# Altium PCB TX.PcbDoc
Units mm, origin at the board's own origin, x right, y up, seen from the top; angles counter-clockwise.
Board outline 26 x 26 mm, 2 copper layers (Top, Bottom), stack 0.323 mm thick; 37 components, 25 nets, 114 pads, 97 vias.
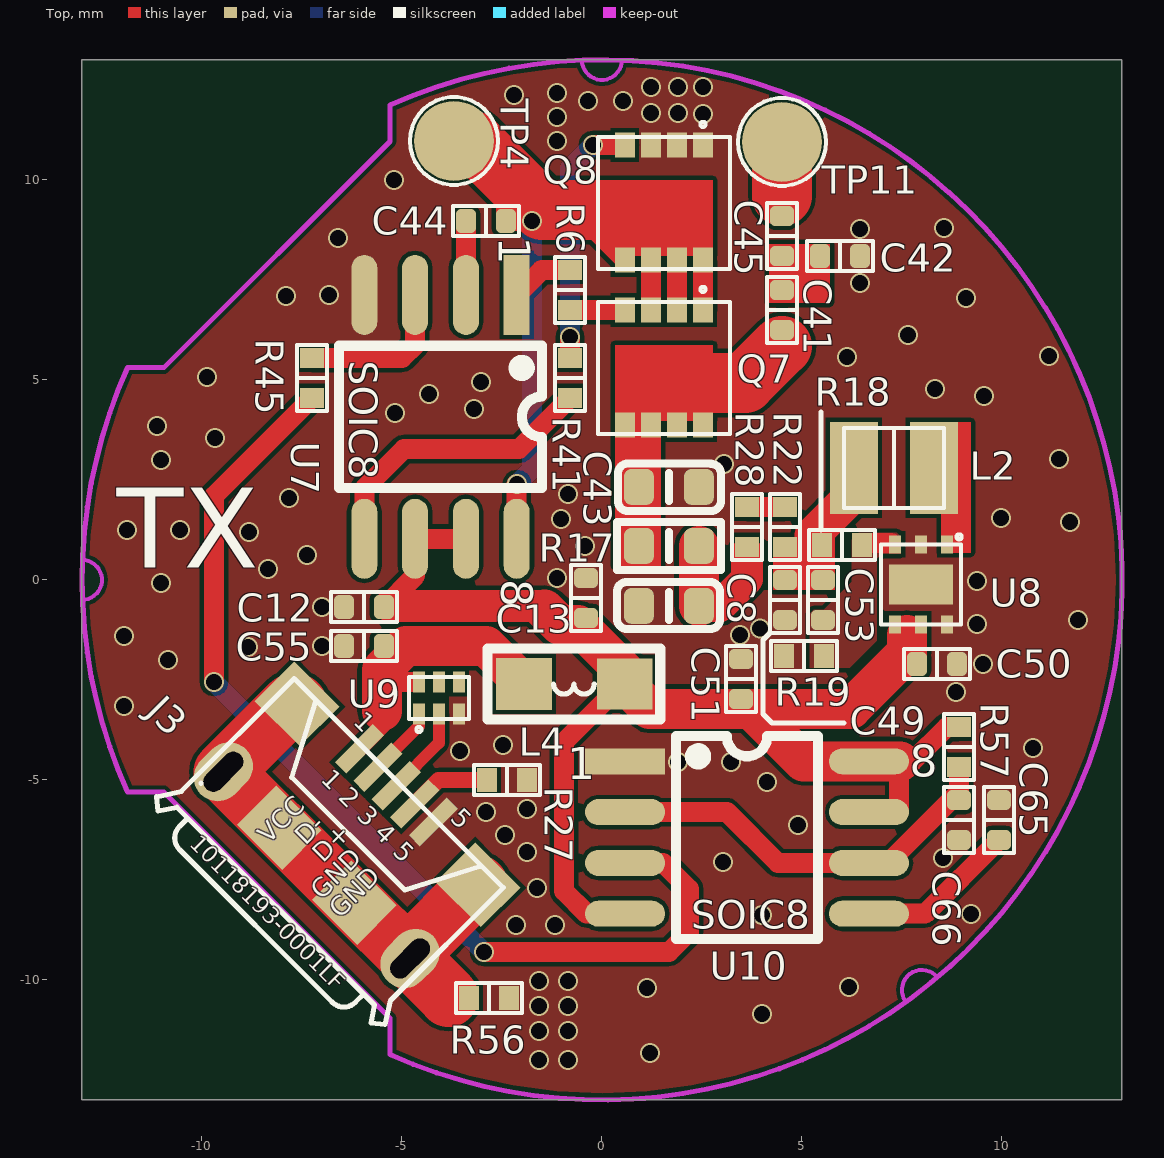
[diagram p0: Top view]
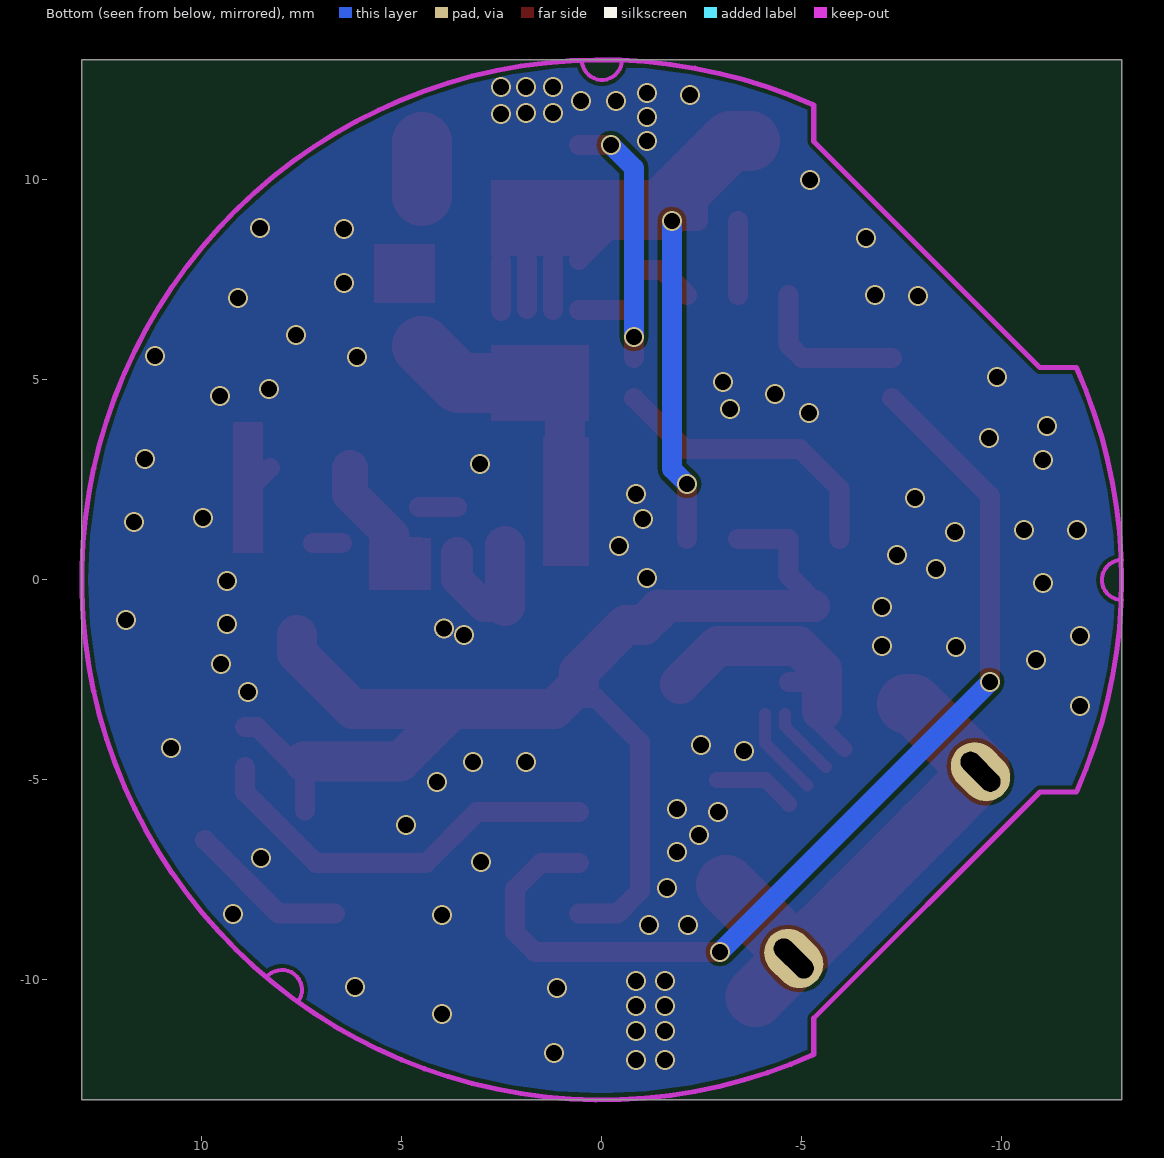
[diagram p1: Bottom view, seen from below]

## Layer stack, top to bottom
Top: signal copper 0.0343
Dielectric: core 0.254, FR-4, Dk 4.3
Bottom: signal copper 0.0343

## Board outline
-13,-13 13,-13 13,-5.875 13,13 -13,13 -13,-13

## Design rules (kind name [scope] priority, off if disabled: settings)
Clearance [All] p1: gap=0.1
Clearance "'Default' PADS rule_18" [All] p2: gap=0.152
Clearance "'Default' PADS rule_15" [IsVia vs IsVia] p3: gap=0.152
ComponentClearance "'Default' PADS rule_12" [All] p1 off: gap=0 collisioncheckmode=3 verticalgap=0 showdistances=FALSE
DiffPairsRouting [All] p1 off: maxlimit=0.254 minlimit=0.254 mostfreqgap=0.254 maxuncoupledlength=12.7
FabricationTestPointUsage TestPointUsage [All] p1 off: valid=0 allowmultiple=FALSE
FabricationTestpoint Testpoint [(IsPad And (OnTopLayer Or OnBottomLayer))] p1 off: side=3 testpointundercomponent=TRUE minsize=1.016 maxsize=2.54 preferedsize=1.524 minholesize=0 maxholesize=1.016 preferedholesize=0.813 testpointgrid=0.025 allowsidetop=TRUE allowsidebottom=TRUE usegrid=TRUE gridtolerance=0
FanoutControl Fanout_BGA [IsBGA] p1 off: bgadir=Out bgaviamode=Centered fanoutstyle=Auto fanoutdirection=Alternating viagrid=0.025 // Fanout_BGA (Default Rule)
FanoutControl Fanout_LCC [IsLCC] p2 off: bgadir=Out bgaviamode=Centered fanoutstyle=Auto fanoutdirection=Alternating viagrid=0.025 // Fanout_LCC (Default Rule)
FanoutControl Fanout_SOIC [IsSOIC] p3 off: bgadir=Out bgaviamode=Centered fanoutstyle=Auto fanoutdirection=Alternating viagrid=0.025 // Fanout_SOIC (Default Rule)
FanoutControl Fanout_Small [(CompPinCount < 5)] p4 off: bgadir=Out bgaviamode=Centered fanoutstyle=Auto fanoutdirection=OutThenIn viagrid=0.025 // Fanout_Small (Default Rule)
FanoutControl Fanout_Default [All] p5 off: bgadir=Out bgaviamode=Centered fanoutstyle=Auto fanoutdirection=Alternating viagrid=0.025 // Fanout_Default (Default Rule)
FlightTimeFalling "'Default' PADS rule_10" [All] p1 off: maximum=10.00
FlightTimeRising "'Default' PADS rule_9" [All] p1 off: maximum=10.00
Height [All] p1 off: minheight=0 maxheight=25.4 prefheight=12.7
HoleSize [All] p1 off: absolutevalues=TRUE maxlimit=2.54 minlimit=0.025 maxpercent=80.000 minpercent=20.000
LayerPairs [All] p1 off: enforce=TRUE
Length "'Default' PADS rule_5" [All] p1 off: maxlimit=1270 minlimit=0
MatchedLengths "'Default' PADS rule_11" [InNetClass('All Nets')] p1 off: tolerance=5.08 checknetsindiffpair=TRUE checkdiffpairvsdiffpair=TRUE checkothers=TRUE
MaxMinImpedance "'Default' PADS rule_8" [All] p1 off: minimum=50.00 maximum=150.0
ParallelSegment "'Default' PADS rule_7" [All] p1 off: limit=25.4 gap=5.08
ParallelSegment "'Default' PADS rule_6" [All] p2 off: limit=25.4 gap=5.08
PasteMaskExpansion [All] p1 off: expansion=0
PlaneClearance "'Default' PADS rule_14" [All] p1 off: clearance=0.152
PlaneConnect "Power Plane Connect Style - from global settings" [All] p1: planeconnectstyle=Direct reliefexpansion=0.508 reliefentries=2 reliefconductorwidth=0.381 reliefairgap=0.254
PolygonConnect [All] p1: connectstyle=Direct reliefconductorwidth=0.254 reliefentries=4 polygonreliefangle="90 Angle" airgapwidth=0.254
RoutingCorners [All] p1 off: cornerstyle=45-Degree minsetback=2.54 maxsetback=2.54
RoutingLayers "'Default' PADS rule_3" [All] p1 off: top layer_v5=TRUE bottom layer_v5=TRUE
RoutingPriority "'Default' PADS rule_2" [All] p1 off: routingpriority=3
RoutingTopology "'Default' PADS rule" [All] p1 off: topology=Shortest
RoutingVias "'Default' PADS rule_4" [All] p1: holewidth=0.94 width=0.4 viastyle="Through Hole" minholewidth=0.2 minwidth=0.3 maxholewidth=2 maxwidth=1.397
SMDToCorner "'Default' PADS rule_16" [All] p1 off: distance=60000
SMDToPlane "'Default' PADS rule_17" [All] p1 off: distance=60000
SolderMaskExpansion [All] p1 off: expansion=0.102
Width "'Default' PADS rule_13" [All] p1: maxlimit=2 minlimit=0.1 preferedwidth=0.2
9 further rules are at their usual default settings.

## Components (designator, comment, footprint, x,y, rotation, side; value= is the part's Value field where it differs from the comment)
C8 "22uF" 0603CS 1.675,-0.65 r0 top
C12 "0.1uF" 0402C -5.95,-0.675 r180 top
C13 "10uF" 0402C -0.4,-0.45 r90 top
C41 "0.047uF" 0402C 4.5,6.75 r90 top
C42 "0.047uF" 0402C 5.95,8.1 r0 top
C43 "22uF" 0603CS 1.675,2.325 r180 top
C44 "0.22uF" 0402C -2.9,8.975 r0 top
C45 "0.01uF" 0402C 4.5,8.6 r90 top
C49 "10uF" 0402C 4.575,-0.5 r270 top
C50 "4.7uF" 0402C 8.375,-2.1 r0 top
C51 "10uF" 0402C 3.475,-2.475 r90 top
C53 "12pF" 0402C 5.525,-0.5 r270 top
C55 "10nF" 0402C -5.95,-1.65 r180 top
C65 "0.1uF" 0402C 9.925,-6 r90 top
C66 "0.1uF" 0402C 8.925,-6 r270 top
J3 "10118193-0001LF" 10118193-0001LF -8.65,-8.65 r315 top
L2 "2.2uH, LQH2HPN2R2MM0L" 2520-1 7.3,2.8 r180 top
L4 "BK2125HS101-T" 0805L -0.7,-2.6 r180 top
Q7 "CSD17308Q3" SSON_3.3*3.3 1.55,5.3 r270 top
Q8 "CSD17308Q3" SSON_3.3*3.3 1.55,9.425 r270 top
R6 "27" 0402R -0.8,7.25 r270 top
R17 "0.02" 0603RS 1.675,0.85 r0 top
R18 "600k" 0402R 6,0.875 r180 top
R19 "100k" 0402R 5.05,-1.9 r0 top
R22 "0" 0402R 4.575,1.325 r90 top
R27 "0" 0402R -2.375,-5 r0 top
R28 "0" 0402R 3.625,1.325 r90 top
R41 "27" 0402R -0.8,5.05 r90 top
R45 "10" 0402R -7.25,5.05 r90 top
R56 "0" 0402R -2.825,-10.45 r0 top
R57 "14.7" 0402R 8.925,-4.175 r90 top
TP4 "Probe_pad_1mm" PAD -3.7,10.975 r90 top
TP11 "Probe_pad_1mm" PAD 4.5,10.95 r0 top
U7 "TPS28225D" SOIC8 -2.13,7.125 r270 top
U8 "MM3472XRRE_SSON-6L" SSON-6L 7.981,-0.112 r270 top
U9 "TPD4E004" SON6 -4.075,-2.95 r90 top
U10 "LMC555" SOIC8 0.579,-4.535 r0 top

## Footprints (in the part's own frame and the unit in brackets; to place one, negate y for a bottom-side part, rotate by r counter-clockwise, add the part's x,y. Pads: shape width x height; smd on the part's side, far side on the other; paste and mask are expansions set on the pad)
0402C [mm]
  rrect50% 0.5x0.6 smd: 1(-0.5,0) 2(0.5,0)
  silkscreen extent -0.82,-0.38 0.82,0.38
0402R [mm]
  rect 0.5x0.6 smd: 1(-0.5,0) 2(0.5,0)
  silkscreen extent -0.82,-0.38 0.82,0.38
0603CS [mm]
  rrect50% 0.75x0.9 smd: 1(-0.75,0) 2(0.75,0)
  silkscreen extent -1.3,-0.58 1.28,0.6
0603RS [mm]
  rrect50% 0.75x0.9 smd: 1(-0.75,0) 2(0.75,0)
  silkscreen extent -1.3,-0.6 1.3,0.6
0805L [mm]
  rect 1.397x1.27 smd: 1(-1.27,0)
  rect 1.4x1.3 smd: 2(1.25,0)
  silkscreen extent -2.16,-0.89 2.16,0.89
2520-1 [mm]
  rect 1.2x2.3 smd: 1(-1,0) 2(1,0)
  silkscreen extent -1.25,-1 1.25,1
10118193-0001LF [mm]
  rect 0.4x1.35 smd: 1(-1.3,4.963) 2(-0.65,4.963) 3(0,4.961) 4(0.65,4.963) 5(1.3,4.975)
  rect 1.6x1.4 smd: 6(-3.2,4.65) 7(3.2,4.65) 8(1.325,2.15) 9(-1.325,2.15)
  oval 1.2x1.6 hole 0.5 slot 1.2 at 90 deg: 8(3.3,2.15) 9(-3.3,2.15)
  silkscreen extent -4.04,0 4.03,5.05
PAD [mm]
  round 2 smd: 1(0,0)
SOIC8 [mm]
  rect 2x0.65 smd: 1(0,0)
  oval 2x0.65 smd: 2(0,-1.27) 3(0,-2.54) 4(0,-3.81) 5(6.096,-3.81) 6(6.096,-2.54) 7(6.096,-1.27) 8(6.096,0)
  silkscreen extent 1.27,-4.44 4.83,0.64
SON6 [mm]
  rect 0.52x0.3 smd: 1(-0.4,0.5) 2(-0.4,0) 3(-0.4,-0.5) 4(0.4,-0.5) 5(0.4,0) 6(0.4,0.5)
  silkscreen extent -0.85,-0.75 0.53,0.75
SSON-6L [mm]
  rect 0.45x0.3 smd: 1(-1,0.65) 2(-1,0) 3(-1,-0.65) 4(1,-0.65) 5(1,0) 6(1,0.65)
  rect 1x1.6 smd: 7(0,0)
  silkscreen extent -1.25,-1 1,1.01
SSON_3.3*3.3 [mm]
  rect 0.63x0.5 smd: 1(-1.45,0.975) 2(-1.45,0.325) 3(-1.45,-0.325) 4(-1.45,-0.975) 5(1.425,-0.975) 6(1.425,-0.325) 7(1.425,0.325) 8(1.425,0.975)
  Top region: -0.575,-1.224 1.325,-1.224 1.325,1.226 -0.575,1.226
  silkscreen extent -2.03,-1.65 1.65,1.65

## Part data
C8 C12 C13 C41 C42 C43 C44 C45 C49 C50 C51 C53 C55 C65 C66: library part CAP_2.2nF_X7R_0603
J3: library part 10118193-0001LF_MUSB_1
L2: library part MLZ1005M2R2W_Ind402_0
L4: library part INDUCTOR/SM
R6 R17 R18 R19 R41 R57: library part RES_10K_0603_THK_1%
R22 R27 R28 R45 R56: library part RES_1oHM_0603
TP4 TP11: library part "TEST POINT"
U7: library part sn74lvc1g74dqer_0
U8: library part MM3472XRRE-6P_4

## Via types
v1: diameter 0.5, hole 0.4, Top to Bottom, tented both sides, 97 vias

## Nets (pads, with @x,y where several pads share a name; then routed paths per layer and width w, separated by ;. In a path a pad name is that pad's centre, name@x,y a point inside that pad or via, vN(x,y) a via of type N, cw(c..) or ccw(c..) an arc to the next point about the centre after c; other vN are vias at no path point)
GND: C8.1 C12.2 C13.2 C42.2 C43.1 C49.2 C50.2 C51.2 C55.2 C65.2 C66.2 J3.5 Q8.1 Q8.2 Q8.3 R19.1 R27.2 R56.2 U7.4 U8.2 U8.6 U8.7 U9.3 U10.1
  other v1: -1.575,-12 -0.85,-12 1.2,-11.825 -1.575,-11.275 -0.85,-11.275 4,-10.85 -1.575,-10.65 -0.85,-10.65 1.125,-10.2 6.175,-10.175 -1.575,-10.025 -0.85,-10.025 -2.15,-8.625 -1.175,-8.625 4,-8.375 9.225,-8.35 -1.625,-7.7 3.025,-7.05 8.525,-6.95 -1.875,-6.8 -2.425,-6.375 4.9,-6.125 -2.9,-5.8 -1.875,-5.725 4.125,-5.05 1.9,-4.55 3.225,-4.55 -3.55,-4.275 10.775,-4.2 -2.475,-4.125 -11.95,-3.15 8.85,-2.8 9.525,-2.1 -10.85,-2 -8.85,-1.675 -7,-1.65 -11.95,-1.4 3.45,-1.375 3.95,-1.216 9.375,-1.1 11.9,-1 -7,-0.675 -11.025,-0.075 9.375,-0.025 -1.125,0.05 -8.35,0.275 -7.375,0.625 -0.425,0.85 -8.825,1.2 -11.875,1.25 -10.55,1.25 11.7,1.45 -1.025,1.525 9.975,1.55 -7.825,2.05 -0.85,2.15 3.05,2.9 -11.025,3 11.425,3.025 -9.675,3.55 -11.125,3.85 -5.175,4.175 -3.2,4.275 9.55,4.6 -4.325,4.65 8.325,4.775 -3.025,4.95 -9.875,5.075 6.125,5.575 11.175,5.6 7.65,6.125 9.1,7.05 -7.9,7.1 -6.825,7.125 6.45,7.425 -6.6,8.55 6.45,8.775 8.55,8.8 -5.2,10 -1.125,10.975 -1.125,11.575 2.525,11.65 1.225,11.675 1.9,11.675 -0.35,11.975 0.525,11.975 -2.2,12.125 -1.125,12.175 1.225,12.325 1.9,12.325 2.525,12.325
NetC8_2: C8.2 R17.2 R28.1 | length 3.6
  Top w0.8: C8.2 2.95,-0.65 3.625,0.025 R28.1@3.625,0.675
  Top w1: C8.2 R17.2
NetC41_1: C41.1 C43.2 Q7.5 Q7.6 Q7.7 Q7.8 R17.1 | length 6.9
  Top w0.5: 0.925,4.025 0.925,4.425
  Top w1: R17.1 C43.2 0.925,4.025
  Top w1.5: 1.525,4.925 3.575,4.925 4.5,5.85
NetC41_2: C41.2 C42.1 C45.1 | length 1.8
  Top w0.5: C41.2 C45.1 C42.1
NetC44_1: C44.1 U7.2 | length 1.8
  Top w0.5: U7.2 C44.1
NetC44_2: C44.2 Q7.1 Q7.2 Q7.3 Q8.5 Q8.6 Q8.7 Q8.8 TP4.1 U7.8 | length 22.4
  Top w0.5: TP4.1@-3.338,10.613 -2.4,9.675 C44.2 v1(-1.75,8.975) -0.4,8.975 Q8.5 ; U7.8 v1@-2.13,2.395 ; Q7.3 Q8.6 ; Q7.2@1.875,6.775 Q8.7@1.875,8.025 ; Q7.1@2.525,6.725 Q8.8@2.525,7.975
  Top w1.5: TP4.1 -3.225,10.975 -1.5,9.25 0.75,9.25
  Bottom w0.5: v1(-2.125,2.4) -1.75,2.775 v1(-1.75,8.975)
NetC45_2: C45.2 TP11.1 | length 1.3
  Top w1.5: 4.5,9.6 TP11.1
NetC49_1: C49.1 C53.1 L2.2 R18.2 R22.1 | length 6.3
  Top w0.5: R18.2@5.262,0.825 R22.1 C49.1 C53.1 ; C53.1@5.575,0.012 R18.2@5.575,0.837
  Top w0.9: 5.075,0.275 5.262,0.463 5.262,1.112 6.3,2.15 L2.2
NetC53_2: C53.2 R18.1 R19.2 U8.3 | length 0.7
  Top w0.5: R18.1@6.5,0.925 U8.3@7.225,0.925
NetC55_1: C55.1 J3.1 L4.2 U9.6 | length 6.9
  Top w0.4: J3.1 -5.225,-3.387
  Top w0.5: -5.2,-2.55 U9.6@-4.675,-2.55
  Top w1: -5.5,-3.275 -5.5,-2.25 -4.9,-1.65 -2.9,-1.65 L4.2
NetC65_1: C65.1 U10.5 | length 4
  Top w0.5: U10.5 8.08,-8.345 C65.1
NetC66_1: C66.1 R57.1 U10.2 U10.6 | length 10.2
  Top w0.5: U10.2 3.13,-5.805 4.4,-7.075 U10.6 7.15,-7.075 8.925,-5.3 R57.1
NetJ3_2: J3.2 U9.1 | length 1.8
  Top w0.3: J3.2 -4.575,-3.656 U9.1
NetJ3_3: J3.3 U9.2 | length 2.2
  Top w0.3: J3.3 -4.075,-4.075 U9.2
NetJ3_4: J3.4 R27.1 | length 2.1
  Top w0.4: J3.4 -4.081,-5 R27.1
NetJ3_6: J3.6 J3.7 J3.8 J3.9 R56.1 | length 13
  Top w1.5: J3.6 -7.766,-3.099 -9.463,-4.796 -8.067,-6.193 -6.193,-8.067 J3.8@-4.796,-9.463 ; -3.834,-10.425 J3.8@-4.796,-9.463 ; J3.7 -4.796,-9.322 J3.8@-4.796,-9.463
NetL2_1: L2.1 U8.1 | length 2.1
  Top w0.5: L2.1 8.725,2.375 U8.1@8.725,0.925
NetQ7_4: Q7.4 R6.2 | length 1.4
  Top w0.5: R6.2 Q7.4
NetQ8_4: Q8.4 R41.2 | length 6.4
  Top w0.5: R41.2 v1(-0.8,6.075) ; v1(-0.225,10.875) Q8.4
  Bottom w0.5: v1(-0.8,6.075) -0.8,10.3 v1(-0.225,10.875)
NetR6_1: R6.1 U7.1 | length 1.6
  Top w0.5: U7.1 -1.505,7.75 R6.1
NetR41_1: R41.1 U7.5 | length 7.3
  Top w0.5: U7.5 -5.94,2.285 -4.95,3.275 -2.075,3.275 R41.1
NetR45_1: R45.1 U10.3 | length 25.9
  Top w0.5: v1(-9.7,-2.55) -9.7,2.1 R45.1 ; v1(-2.95,-9.3) 1.675,-9.3 2.175,-8.8 2.175,-7.725 1.525,-7.075 U10.3
  Bottom w0.5: v1(-9.7,-2.55) v1(-2.95,-9.3)
NetR45_2: R45.2 U7.3 | length 4
  Top w0.5: R45.2 -5,5.55 -4.67,5.88 U7.3
VCC_COIL: R22.2 R28.2 | length 0.9
  Top w0.5: R28.2 R22.2
VCC_USB: C12.1 C13.1 C50.1 C51.1 L4.1 R57.2 U7.6 U7.7 U8.4 U8.5 U10.4 U10.7 U10.8 | length 32.9
  Top w0.5: C12.1 -4.67,0.105 U7.6 U7.7 ; L4.1@0.57,-2.95 0.15,-2.95 -0.95,-4.05 -0.95,-7.775 -0.38,-8.345 U10.4 ; U10.7@7.425,-5.77 U10.8@7.425,-4.5 ; 7.765,-4.535 8.625,-3.675 R57.2
  Top w0.8: C12.1@-5.3,-0.65 -1.525,-0.65
  Top w1: -1.433,-0.742 -1.05,-1.125 -0.6,-1.125 0.57,-2.295 L4.1 1.195,-3.225 3.725,-3.225 ; U10.8@7.45,-4.535 5.035,-4.535 3.725,-3.225 ; 7.625,-1.375 7.625,-1.825 6.225,-3.225 3.725,-3.225
pads on no net: U9.4 U9.5

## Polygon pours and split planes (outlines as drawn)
GND on Top "Top Layer-No Net" (solid, remove dead copper, pour order 13): -13,-13 13,-13 13,-12.975 13,-12.45 13,13 -13,13 -13,-13
NetC53_2 on Top "Top Layer-No Net" (solid, remove dead copper, pour order 12): 6.2,-2.2 6.875,-1.525 6.875,0.525 7,0.65 7.475,0.65 7.475,1.075 7.375,1.175 6.425,1.175 6.25,1 6.25,-0.05 5.55,-0.75 5.3,-0.75 5.2,-0.85 5.2,-2.2
GND on Bottom "Top Layer-No Net" (solid, remove dead copper, pour order 14): 13,-13 -13,-13 -13,-12.975 -13,-12.45 -13,13 13,13 13,-13

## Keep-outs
Keep-Out Layer:
  lines w0.1: -13,-0.5 ccw(c-13,0) -13,0.5 ; -0.5,13 ccw(c0,13) 0.5,13 ; 7.6,-10.55 cw(c8,-10.25) 8.39,-9.938
  lines w0.127: -11.862,-5.301 cw(c0.007,0.002) -11.862,5.305 -10.953,5.305 -5.297,10.962 -5.297,11.871 cw(c0.007,0.002) -5.297,-11.867 -5.297,-10.958 -10.953,-5.301 -11.862,-5.301

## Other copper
Top:
  rectangle net NetC41_2: 4.175,6.925 5.7,8.4
  rectangle net NetL2_1: 8.475,0.675 9.225,3.95
  rectangle net NetC49_1: 4.275,-0.25 5.825,1.05
  rectangle net NetC41_1: 0.325,0.35 1.475,3.575

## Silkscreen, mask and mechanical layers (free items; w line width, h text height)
Silkscreen Top:
  circle w0.1: c4.5,10.95 r1.1
  circle w0.1: c-3.7,10.975 r1.1
  lines w0.127: 4.2,-1.325 4.025,-1.5 4.025,-3.35 4.25,-3.575 6.05,-3.575 ; 5.475,1.25 5.475,4.2
  text "TX" at -12.125,0.3 h2
Assembly Drawing Top:
  lines w0.1: -13,-0.5 ccw(c-13,0) -13,0.5 ; -0.5,13 ccw(c0,13) 0.5,13 ; 7.6,-10.55 cw(c8,-10.25) 8.39,-9.938
  lines w0.127: -11.862,-5.301 cw(c0.007,0.002) -11.862,5.305 -10.953,5.305 -5.297,10.962 -5.297,11.871 cw(c0.007,0.002) -5.297,-11.867 -5.297,-10.958 -10.953,-5.301 -11.862,-5.301
  lines w0.254: -16.508,-11.476 -16,-13 ; -16.508,11.476 -16,13 ; -16.254,-13 -15.746,-13 ; -16.254,13 -15.746,13 ; -16,-5.104 -16,-13 ; -16,5.104 -16,13 ; -15.492,-11.476 -16,-13 ; -15.492,11.476 -16,13 ; -13,-15.254 -13,-14.746 ; -11.476,-15.508 -13,-15 ; -11.476,-14.492 -13,-15 ; -5.104,-15 -13,-15 ; 5.104,-15 13,-15 ; 11.476,-15.508 13,-15 ; 11.476,-14.492 13,-15 ; 13,-15.254 13,-14.746
  text "26 (mm)" at -15.086,-4.85 h1.52 r90
  text ".Printout_Name" at -12.85,-13.975 h0.7
  text "26 (mm)" at -4.85,-15.914 h1.52
Drill Drawing:
  text ".Legend" at 13.375,-12.9 h0.7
